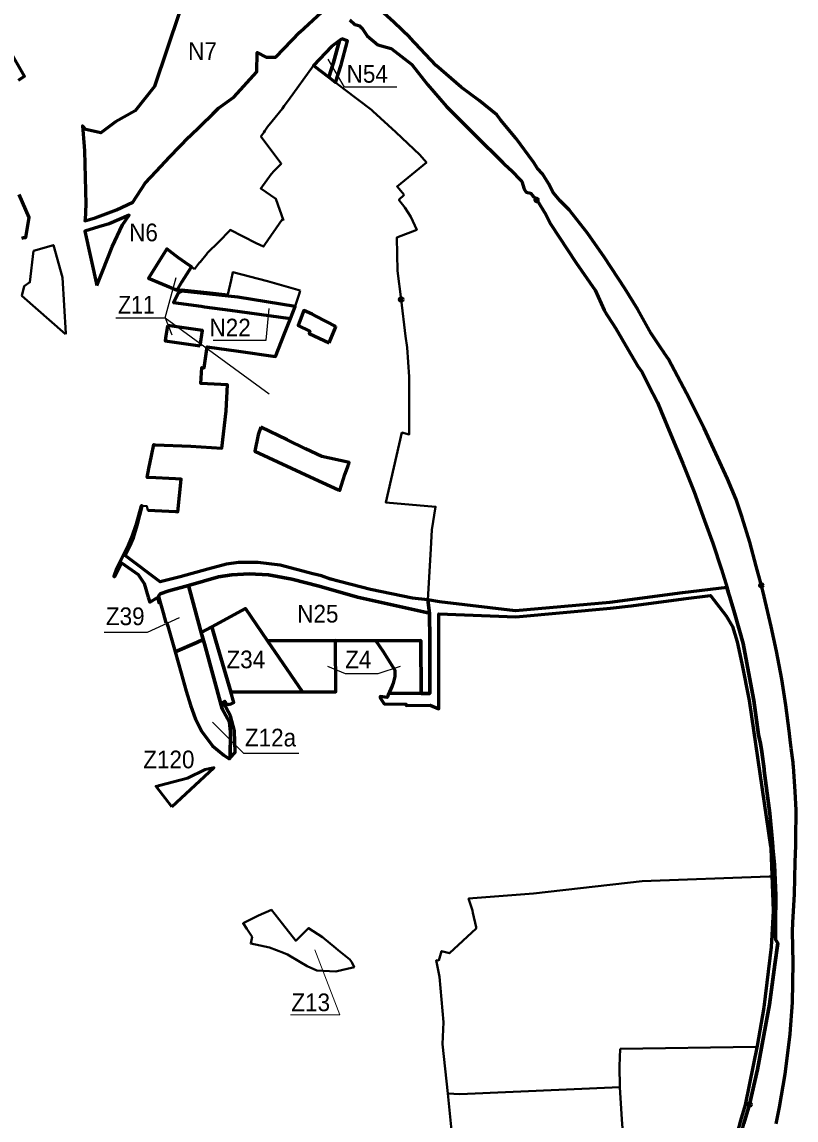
# Model space of a CAD drawing. Extents: x -650277 to -643422, y -1073980 to -1066720.
# Drawn here: x -646020 to -644970, y -1070696 to -1069207 of the extents above; entities that cross this region are included whole.
import ezdxf

# ---------------------------------------------------------------- set-up
doc = ezdxf.new("R2010")
doc.units = 0
doc.header["$LTSCALE"] = 9.6
doc.header["$PDMODE"] = 32
doc.header["$PDSIZE"] = 4.8
for name, color, linetype, lineweight in [('1', 7, 'Continuous', 60), ('11', 7, 'Continuous', 60), ('15', 7, 'Continuous', 60), ('2', 7, 'Continuous', 40), ('3', 7, 'Continuous', 60), ('40', 7, 'Continuous', 60), ('42', 7, 'Continuous', 60), ('59', 7, 'Continuous', 25), ('60', 7, 'Continuous', 60), ('63', 7, 'Continuous', 25), ('7', 7, 'Continuous', 60)]:
    doc.layers.add(name, color=color, linetype=linetype, lineweight=lineweight)

msp = doc.modelspace()

# ---------------------------------------------------------------- linework, layer by layer
at = {"layer": '1'}
msp.add_line((-645623.75, -1069825.97), (-645590.964, -1069841.09), dxfattribs=at)
at = {"layer": '1', "lineweight": 40}
msp.add_line((-645726.542, -1069939.398), (-645742.967, -1069941.862), dxfattribs=at)
for points in [[(-645668.722, -1069398.75), (-645696.19, -1069362.01), (-645692.38, -1069356.67), (-645690.81, -1069354.28), (-645687.22, -1069349), (-645680.8, -1069341.08), (-645667, -1069324.06), (-645664.89, -1069320.2), (-645658.9, -1069312.83), (-645625.11, -1069265.42), (-645604.114, -1069281.49), (-645594.94, -1069288.511)], [(-645594.94, -1069288.511), (-645583.13, -1069297.55), (-645546.19, -1069325.81), (-645544.26, -1069327.35), (-645513.41, -1069356.18), (-645480.72, -1069386.96), (-645471.738, -1069397.026), (-645511.464, -1069429.794), (-645501.878, -1069440.838)], [(-645665.58, -1069475.61), (-645675.91, -1069446.56), (-645696.45, -1069432.21), (-645682.28, -1069412.88), (-645678.06, -1069408.54), (-645668.61, -1069398.9), (-645668.722, -1069398.75)], [(-645501.878, -1069440.838), (-645508.994, -1069447.955), (-645501, -1069458), (-645493, -1069471), (-645484.783, -1069488.256), (-645512, -1069499), (-645511, -1069544), (-645506, -1069583)], [(-645786.388, -1069541.673), (-645779.376, -1069532.962), (-645778.754, -1069532.198), (-645769.369, -1069520.672), (-645768.995, -1069520.305), (-645752.715, -1069504.328), (-645738.986, -1069489.868), (-645737.897, -1069488.534), (-645702.82, -1069506.64), (-645692.87, -1069511.229), (-645690.84, -1069508.32), (-645667.31, -1069474.6), (-645665.58, -1069475.61)], [(-645836.44, -1069534.5), (-645824.05, -1069514.34), (-645811.75, -1069523.81), (-645808.1, -1069526.61), (-645799.07, -1069532.8), (-645790.62, -1069538.59), (-645786.388, -1069541.673)], [(-645810.08, -1069570.39), (-645848.78, -1069553.91), (-645836.44, -1069534.5)], [(-645643.16, -1069570.6), (-645687.29, -1069558.04), (-645734.5, -1069545.89), (-645736.8, -1069556.91), (-645741.14, -1069576.19), (-645769.04, -1069573), (-645803.513, -1069569.263), (-645810.08, -1069570.39)], [(-645676.34, -1069660.28), (-645670.23, -1069644.67), (-645664.19, -1069629.24), (-645657.52, -1069612.2), (-645656.15, -1069608.71), (-645649.91, -1069592.39), (-645648.68, -1069589.06), (-645644.56, -1069575.61), (-645643.16, -1069570.6)], [(-645506, -1069583), (-645500.137, -1069632.833), (-645500.137, -1069632.833)], [(-645500.137, -1069632.833), (-645498, -1069648), (-645495, -1069688), (-645495, -1069744), (-645495, -1069766), (-645504.976, -1069763.332), (-645527, -1069858), (-645459.312, -1069864.01), (-645464.288, -1069895.362), (-645465.756, -1069921.035), (-645469.701, -1069990.011)], [(-645839.721, -1069780.247), (-645839.658, -1069779.835), (-645791.2, -1069781.92), (-645749.48, -1069784.61), (-645743.36, -1069733.7), (-645743.01, -1069730.72), (-645741.43, -1069698.68), (-645763.24, -1069697.58), (-645777.62, -1069696.85), (-645776.45, -1069675.26), (-645773.02, -1069675.47), (-645769.36, -1069648), (-645769.264, -1069647.213), (-645726.57, -1069653.22), (-645676.34, -1069660.28)], [(-645804.185, -1069825.84), (-645804.28, -1069826.76), (-645812.18, -1069826.3), (-645847.62, -1069824.26), (-645850.63, -1069824.09), (-645848.35, -1069812.09), (-645844.57, -1069795.07), (-645841.41, -1069779.76), (-645839.658, -1069779.835), (-645839.721, -1069780.247)], [(-645742.967, -1069941.862), (-645768.424, -1069948.431), (-645833, -1069966), (-645880.431, -1069930.3), (-645874.219, -1069917.496), (-645869.262, -1069905.935), (-645863.95, -1069889.468), (-645857.289, -1069863.338), (-645857.204, -1069862.954), (-645850.92, -1069863.41), (-645849.79, -1069868.4), (-645808.84, -1069870.75), (-645808.28, -1069865.39), (-645804.185, -1069825.84)], [(-645469.701, -1069990.011), (-645490.814, -1069988.074), (-645547.4, -1069976.382), (-645614.072, -1069957.797), (-645625.979, -1069954.92), (-645670.325, -1069943.002), (-645699.889, -1069939.714), (-645726.542, -1069939.398)]]:
    msp.add_lwpolyline(points, dxfattribs=at)
at = {"layer": '1'}
for points in [[(-645836.44, -1069534.5), (-645848.78, -1069553.91), (-645810.08, -1069570.39), (-645803.07, -1069558.62), (-645790.62, -1069538.59), (-645799.07, -1069532.8), (-645808.1, -1069526.61), (-645811.75, -1069523.81), (-645824.05, -1069514.34)], [(-645639.638, -1070114.895), (-645594.733, -1070114.868), (-645595.2, -1070045.403), (-645687.31, -1070045.724)], [(-645522.587, -1070116.952), (-645478.664, -1070117.114), (-645479.429, -1070045.409), (-645540.433, -1070045.752), (-645530.3, -1070060.08), (-645514.49, -1070085.4), (-645514.56, -1070090.91), (-645514.61, -1070094.35), (-645517.02, -1070103.08), (-645518.35, -1070106.87), (-645521.73, -1070114.83)]]:
    msp.add_lwpolyline(points, close=True, dxfattribs=at)
for points in [[(-645594.58, -1069619.56), (-645621.56, -1069605.68), (-645626.95, -1069602.91), (-645638.203, -1069597.8), (-645645.715, -1069618.085), (-645629.78, -1069626.03), (-645630.93, -1069628.84), (-645603.7, -1069641.75)], [(-645849.79, -1069868.4), (-645811.848, -1069870.577), (-645808.84, -1069870.75), (-645804.28, -1069826.76), (-645812.18, -1069826.3), (-645847.62, -1069824.26), (-645850.63, -1069824.09), (-645848.35, -1069812.09), (-645844.57, -1069795.07), (-645841.41, -1069779.76), (-645839.658, -1069779.835), (-645791.2, -1069781.92), (-645749.48, -1069784.61), (-645743.36, -1069733.7), (-645741.43, -1069698.68), (-645777.62, -1069696.85), (-645776.45, -1069675.26), (-645773.02, -1069675.47), (-645769.264, -1069647.213), (-645726.57, -1069653.22), (-645676.34, -1069660.28), (-645664.19, -1069629.24), (-645656.15, -1069608.71)], [(-645823.082, -1069618.279), (-645823.13, -1069618.452), (-645825.295, -1069632.053), (-645826.133, -1069638.843), (-645826.151, -1069639.057), (-645778.45, -1069645.92)], [(-645778.45, -1069645.92), (-645775.46, -1069625.13), (-645823.082, -1069618.279)], [(-645603.7, -1069641.75), (-645594.818, -1069620.139), (-645594.58, -1069619.56)], [(-645696.517, -1069756.039), (-645700.028, -1069766.286), (-645704.355, -1069788.786), (-645623.75, -1069825.97)], [(-645578.134, -1069803.73), (-645613.84, -1069795.78), (-645635.79, -1069785.23), (-645660.57, -1069773.31), (-645696.517, -1069756.039)], [(-645590.964, -1069841.09), (-645589.23, -1069841.89), (-645582.31, -1069820.05), (-645577.52, -1069807.26), (-645576.34, -1069804.13), (-645578.134, -1069803.73)], [(-645772.853, -1070049.868), (-645774.423, -1070044.167), (-645783.063, -1070047.855), (-645812.76, -1070060.53)], [(-645737.756, -1070204.389), (-645737.624, -1070169.544), (-645738.79, -1070156.281), (-645748.62, -1070137.889), (-645772.853, -1070049.868)], [(-645812.76, -1070060.53), (-645804.52, -1070089.63), (-645797.66, -1070113.88), (-645791.72, -1070133.09), (-645784.83, -1070151.9), (-645784.83, -1070151.9)], [(-645784.83, -1070151.9), (-645776.26, -1070168.94), (-645761.78, -1070188.29), (-645746.73, -1070201.04), (-645739.12, -1070205.9), (-645737.756, -1070204.389)]]:
    msp.add_lwpolyline(points, dxfattribs=at)
at = {"layer": '1', "lineweight": 53}
msp.add_lwpolyline([(-645816.9, -1070270.96), (-645760.05, -1070217.79), (-645760.91, -1070217.98), (-645772.08, -1070220.39), (-645795.85, -1070231.81), (-645833.92, -1070241.96), (-645838.53, -1070243.19)], close=True, dxfattribs=at)
at = {"layer": '1'}
msp.add_point((-645506, -1069583), dxfattribs=at)
at = {"layer": '11'}
msp.add_lwpolyline([(-645639.638, -1070114.895), (-645687.31, -1070045.724), (-645717.36, -1070002.12), (-645762.868, -1070026.606), (-645757.215, -1070045.97), (-645737.075, -1070114.955)], close=True, dxfattribs=at)
at = {"layer": '15'}
for points in [[(-645586.39, -1069229.32), (-645589.844, -1069231.908), (-645597.738, -1069261.522), (-645604.114, -1069281.49), (-645594.94, -1069288.511), (-645587.298, -1069264.578), (-645578.713, -1069232.375)], [(-645735.532, -1069956.306), (-645712.222, -1069954.725), (-645686.147, -1069956.306), (-645654.145, -1069962.232), (-645617.403, -1069971.714), (-645565.133, -1069986.508), (-645467.472, -1070008.38), (-645469.701, -1069990.011), (-645490.814, -1069988.074), (-645547.4, -1069976.382), (-645601.753, -1069962.317), (-645614.072, -1069957.797), (-645625.979, -1069954.92), (-645670.325, -1069943.002), (-645699.889, -1069939.714), (-645726.542, -1069939.398), (-645742.967, -1069941.862), (-645768.424, -1069948.431), (-645806, -1069959), (-645833, -1069966), (-645880.431, -1069930.3), (-645874.219, -1069917.496), (-645869.262, -1069905.935), (-645863.95, -1069889.468), (-645857.289, -1069863.338), (-645857.204, -1069862.954), (-645858.78, -1069862.84), (-645865.78, -1069888.76), (-645870.89, -1069903.5), (-645876.15, -1069916.47), (-645892.09, -1069947.98), (-645895.66, -1069958.42), (-645894.25, -1069958.7), (-645885.422, -1069940.184), (-645862.782, -1069955.809), (-645854.81, -1069967.927), (-645849.1, -1069986.42), (-645847.135, -1069993.337), (-645836.64, -1069987.18), (-645834.65, -1069994.21), (-645833.32, -1069991.86), (-645835, -1069985), (-645833, -1069982), (-645821, -1069978), (-645794.679, -1069970.596), (-645753.706, -1069959.071)]]:
    msp.add_lwpolyline(points, close=True, dxfattribs=at)
for points in [[(-646025.14, -1069285.394), (-646017.15, -1069280.19), (-646037.99, -1069242.88)], [(-645061.76, -1069981.21), (-645064.052, -1069973.429), (-645124.233, -1069980.695), (-645222.809, -1069993.701), (-645350.784, -1070005.227), (-645453.852, -1069992.968), (-645469.701, -1069990.011), (-645467.472, -1070008.38), (-645467.068, -1070044.959), (-645466.96, -1070117.157), (-645478.664, -1070117.114), (-645522.587, -1070116.952), (-645524.82, -1070122.48), (-645534.63, -1070121.09), (-645534.7, -1070122.95), (-645529.17, -1070131.4), (-645499.276, -1070131.652), (-645499.142, -1070133.293), (-645466.862, -1070133.219), (-645454.881, -1070137.836), (-645455.073, -1070009.111), (-645350.591, -1070013.242), (-645221.99, -1070001.66), (-645194.003, -1069998.417), (-645123.206, -1069988.629), (-645086.484, -1069984.195), (-645065.235, -1070011.695)], [(-645033.53, -1070674.55), (-645022.64, -1070626.93), (-645014.07, -1070580.72), (-645006.44, -1070538.78), (-644998.92, -1070484.58), (-644995.14, -1070455.72), (-644998.17, -1070450.59), (-644998.25, -1070430.5), (-644997.87, -1070391.16), (-644999.47, -1070349.63), (-645001.64, -1070326.4), (-645001.81, -1070324.58), (-645002.308, -1070319.268), (-645005.98, -1070280.14), (-645013.51, -1070222.04), (-645013.77, -1070220.04), (-645016.92, -1070196.32), (-645018.56, -1070184.92), (-645021.14, -1070173.07), (-645027.49, -1070126.56), (-645032.21, -1070102.73), (-645042.27, -1070049.23), (-645047.28, -1070031.83), (-645054.73, -1070004.56), (-645060.612, -1069985.022), (-645061.76, -1069981.21)], [(-645065.235, -1070011.695), (-645056.555, -1070026.163), (-645050.293, -1070047.035), (-645043.92, -1070076.344), (-645034.122, -1070126.616), (-645004.791, -1070324.889), (-645004.523, -1070326.697)], [(-645757.215, -1070045.97), (-645762.868, -1070026.606), (-645777.143, -1070034.287), (-645772.853, -1070049.868), (-645748.62, -1070137.889)], [(-645737.63, -1070147.39), (-645747.67, -1070129.14), (-645745.29, -1070127.83), (-645744.73, -1070129), (-645743.87, -1070130.15), (-645742.67, -1070131.07), (-645741.83, -1070131.53), (-645740.89, -1070131.8), (-645739.41, -1070131.93), (-645738.41, -1070131.78), (-645737.48, -1070131.45), (-645734.77, -1070130.18), (-645732.91, -1070129.5), (-645737.075, -1070114.955), (-645757.215, -1070045.97)], [(-645748.62, -1070137.889), (-645738.79, -1070156.281), (-645737.624, -1070169.544), (-645737.756, -1070204.389)], [(-645737.756, -1070204.389), (-645731.3, -1070197.24), (-645731.94, -1070167.87), (-645737.63, -1070147.39)], [(-645004.523, -1070326.697), (-645004.434, -1070327.302), (-645001.312, -1070412.099), (-645004.327, -1070461.264), (-645014.277, -1070543.11), (-645023.048, -1070595.033), (-645039.574, -1070675.065)], [(-645039.574, -1070675.065), (-645045.493, -1070696.321), (-645059.308, -1070747.712), (-645059.403, -1070749.195), (-645053.21, -1070749.75), (-645052.4, -1070746.427), (-645046.63, -1070722.77), (-645041, -1070700.44), (-645033.53, -1070674.55)]]:
    msp.add_lwpolyline(points, dxfattribs=at)
msp.add_point((-645033.53, -1070674.55), dxfattribs=at)
at = {"layer": '2'}
for points in [[(-646017.39, -1069564.94), (-646017.39, -1069564.94), (-646009.52, -1069559.6), (-646004.7, -1069517.16)], [(-646004.7, -1069517.16), (-645977.73, -1069509.11), (-645965.36, -1069552.99), (-645960.78, -1069628.91), (-645961.36, -1069630.05)], [(-645961.36, -1069630.05), (-646020.4, -1069578.04), (-646017.39, -1069564.94)], [(-645023.048, -1070595.033), (-645014.277, -1070543.11), (-645004.327, -1070461.264), (-645001.312, -1070412.099), (-645003.03, -1070365.427), (-645003.102, -1070365.432), (-645006.86, -1070365.38), (-645179.26, -1070371.74), (-645326.62, -1070388.32), (-645414.65, -1070395.37), (-645409.38, -1070411.41), (-645408.66, -1070414.62), (-645404.34, -1070433.93), (-645404.4, -1070435.88), (-645440.61, -1070469.53), (-645451.226, -1070466.394), (-645455.09, -1070479.21), (-645458.46, -1070478.86), (-645454.02, -1070501.52), (-645448.36, -1070563), (-645449.82, -1070592.72), (-645442.834, -1070659.455)], [(-645209.41, -1070651.2), (-645209.79, -1070622.69), (-645208.96, -1070599.22)], [(-645208.96, -1070599.22), (-645025.12, -1070596.42), (-645023.346, -1070596.478), (-645023.048, -1070595.033)], [(-645442.834, -1070659.455), (-645426.34, -1070660.33), (-645209.41, -1070651.2)]]:
    msp.add_lwpolyline(points, dxfattribs=at)
for points in [[(-645594.769, -1070494.065), (-645577.47, -1070490.3), (-645571.13, -1070488.89), (-645569.97, -1070488.3), (-645572.86, -1070481.41), (-645575.7, -1070477.77), (-645591.49, -1070465.19), (-645594.62, -1070462.7), (-645612.77, -1070447.82), (-645631.63, -1070435.3), (-645636.42, -1070439.93), (-645648.9, -1070452.38), (-645666.99, -1070429.58), (-645682.02, -1070410.65), (-645699.33, -1070418.25), (-645714.74, -1070425.84), (-645720.48, -1070428.75), (-645715.56, -1070436.27), (-645708.28, -1070447.28), (-645710.14, -1070456.31), (-645684.78, -1070461.52), (-645665.6, -1070469.04), (-645660.29, -1070471.12), (-645643.4, -1070481.02), (-645633.35, -1070486.91), (-645620.22, -1070493)], [(-645442.836, -1070659.455), (-645426.34, -1070660.33), (-645209.41, -1070651.2), (-645206.7, -1070694.76), (-645204.66, -1070718.51), (-645203.13, -1070749.36), (-645202.96, -1070752.89), (-645275.236, -1070750.954), (-645282, -1070742), (-645301, -1070736), (-645324, -1070736), (-645379, -1070743), (-645415, -1070737), (-645435.711, -1070727.497)]]:
    msp.add_lwpolyline(points, close=True, dxfattribs=at)
at = {"layer": '3'}
for points in [[(-645794.679, -1069970.596), (-645821, -1069978), (-645833, -1069982), (-645835, -1069985), (-645833.32, -1069991.86)], [(-645777.143, -1070034.287), (-645786.238, -1070001.251), (-645794.679, -1069970.596)], [(-645833.32, -1069991.86), (-645828.9, -1070007.76), (-645825.08, -1070021.52)], [(-645825.08, -1070021.52), (-645823.76, -1070021.67), (-645822.549, -1070025.948), (-645812.76, -1070060.53), (-645783.063, -1070047.855), (-645774.423, -1070044.167), (-645777.143, -1070034.287)]]:
    msp.add_lwpolyline(points, dxfattribs=at)
at = {"layer": '40'}
for points in [[(-645698.83, -1069602.85), (-645656.15, -1069608.71), (-645649.91, -1069592.39), (-645727.71, -1069579.61), (-645803.33, -1069571.62), (-645808.18, -1069573.7), (-645814.82, -1069586.81), (-645777.26, -1069592.07), (-645772.58, -1069592.73), (-645738.13, -1069597.46)], [(-645595.2, -1070045.403), (-645479.429, -1070045.409), (-645478.664, -1070117.114), (-645466.96, -1070117.157), (-645467.068, -1070044.959), (-645467.472, -1070008.38), (-645565.133, -1069986.508), (-645617.403, -1069971.714), (-645654.145, -1069962.232), (-645686.147, -1069956.306), (-645712.222, -1069954.725), (-645735.532, -1069956.306), (-645753.706, -1069959.071), (-645794.679, -1069970.596), (-645786.238, -1070001.251), (-645777.143, -1070034.287), (-645762.868, -1070026.606), (-645717.36, -1070002.12), (-645687.31, -1070045.724)]]:
    msp.add_lwpolyline(points, close=True, dxfattribs=at)
at = {"layer": '42'}
msp.add_lwpolyline([(-645604.114, -1069281.49), (-645597.738, -1069261.522), (-645589.844, -1069231.908), (-645600.55, -1069239.93), (-645625.11, -1069265.42)], close=True, dxfattribs=at)
for points in [[(-646017.63, -1069499.08), (-646017.63, -1069499.08), (-646015.16, -1069498.74), (-646010.65, -1069471.91), (-646023.96, -1069440.34)], [(-646020.75, -1069500), (-646017.63, -1069499.08)]]:
    msp.add_lwpolyline(points, dxfattribs=at)
at = {"layer": '59', "lineweight": 13}
msp.add_lwpolyline([(-645656, -1070553), (-645589, -1070553), (-645623, -1070465)], dxfattribs=at)
at = {"layer": '60'}
for points in [[(-645575.58, -1069203.57), (-645568.9, -1069209.87), (-645567.07, -1069210.45), (-645562.17, -1069212.02), (-645560.72, -1069214.25), (-645559.33, -1069214.54), (-645552.2, -1069225.59), (-645537.44, -1069237.41), (-645519.59, -1069242.38), (-645491.63, -1069264.25), (-645470.44, -1069291.24), (-645444.62, -1069321.35), (-645405.7, -1069360.27), (-645368.13, -1069397.37), (-645358.04, -1069406.84), (-645342.49, -1069423.06), (-645339.31, -1069433.27), (-645336.66, -1069437.47), (-645330.57, -1069438.89), (-645327.2, -1069442.53), (-645323.36, -1069445.79), (-645322.13, -1069447.96)], [(-645017.46, -1069970.61), (-645018.28, -1069967.49), (-645024.45, -1069944.43), (-645032.85, -1069912.07), (-645043.5, -1069878.37), (-645051.78, -1069854.2), (-645063.26, -1069825.99), (-645095.1, -1069757.62), (-645118.98, -1069710.08), (-645143.56, -1069664.05), (-645148.8, -1069656.1), (-645150.3, -1069653.84), (-645153.33, -1069649.24), (-645166.67, -1069629), (-645184.88, -1069596.58), (-645202.56, -1069568.23), (-645230.1, -1069525.98), (-645253.4, -1069493.06), (-645278.31, -1069461.33), (-645281.4, -1069458.4), (-645290.5, -1069449.03), (-645299.61, -1069437.97), (-645306.16, -1069425.55), (-645314.14, -1069412.54), (-645321.1, -1069405.21), (-645326.59, -1069396.64), (-645350.63, -1069363.98), (-645371.12, -1069339.47), (-645376.38, -1069332.65), (-645400.07, -1069313.32), (-645424.8, -1069295.24), (-645458.45, -1069265.56), (-645494.13, -1069227.63), (-645515.89, -1069206.66), (-645534.25, -1069190.56)], [(-645322.13, -1069447.96), (-645309.62, -1069467.79), (-645303.57, -1069480.49), (-645268.57, -1069533.23), (-645242.75, -1069570.26), (-645230.42, -1069597.39), (-645227.27, -1069602.68), (-645225.7, -1069605.32), (-645214.76, -1069622.37), (-645198.41, -1069650.49), (-645185.17, -1069673.38), (-645179.12, -1069681.3), (-645170.3, -1069698.91), (-645158.43, -1069722.61), (-645153.44, -1069734.71), (-645140.27, -1069766.68), (-645123.84, -1069805.38), (-645108.74, -1069843.58), (-645094.42, -1069882.65), (-645083.31, -1069913.37), (-645071.53, -1069948.89), (-645063.96, -1069973.73), (-645063.23, -1069976.2), (-645062.57, -1069978.46)], [(-645062.57, -1069978.46), (-645061.76, -1069981.21), (-645060.612, -1069985.022), (-645054.73, -1070004.56), (-645047.28, -1070031.83), (-645042.27, -1070049.23), (-645032.21, -1070102.73), (-645027.49, -1070126.56), (-645021.14, -1070173.07), (-645018.56, -1070184.92), (-645016.92, -1070196.32), (-645013.77, -1070220.04), (-645013.51, -1070222.04), (-645005.98, -1070280.14), (-645002.308, -1070319.268), (-645001.81, -1070324.58), (-645001.64, -1070326.4), (-644999.47, -1070349.63), (-644997.87, -1070391.16), (-644998.25, -1070430.5), (-644998.17, -1070450.59), (-644995.14, -1070455.72), (-644998.92, -1070484.58), (-645006.44, -1070538.78), (-645014.07, -1070580.72), (-645022.64, -1070626.93), (-645033.53, -1070674.55)], [(-644996.88, -1070059.73), (-645004.02, -1070026.44), (-645010.54, -1069999.3), (-645015.548, -1069978.177), (-645016.01, -1069976.23), (-645016.89, -1069972.82), (-645017.46, -1069970.61)], [(-644997.14, -1070700.88), (-644992.6, -1070677.92), (-644985.04, -1070633.43), (-644978.44, -1070578.56), (-644975.05, -1070536.16), (-644974.44, -1070482.48), (-644975.29, -1070440.14), (-644974.69, -1070427.86), (-644972.48, -1070389.15), (-644971.37, -1070345.98), (-644970.61, -1070323.44), (-644970.55, -1070321.56), (-644970.524, -1070315.358), (-644970.36, -1070275.49), (-644971.47, -1070250.14), (-644974, -1070216.2), (-644974.29, -1070213.17), (-644974.49, -1070210.98), (-644976.94, -1070191.41), (-644978.49, -1070180.05), (-644979.57, -1070167.9), (-644984.21, -1070132.81), (-644989.62, -1070097.79), (-644996.88, -1070059.73)], [(-645033.53, -1070674.55), (-645041, -1070700.44)]]:
    msp.add_lwpolyline(points, dxfattribs=at)
for p in [(-645322.13, -1069447.96), (-645017.46, -1069970.61), (-645033.53, -1070674.55)]:
    msp.add_point(p, dxfattribs=at)
at = {"layer": '63'}
for q in [(-645817, -1069631), (-645685, -1069711)]:
    msp.add_line((-645826, -1069608), q, dxfattribs=at)
for points in [[(-645512, -1069295), (-645583, -1069295), (-645605, -1069257)], [(-645893, -1069608), (-645826, -1069608), (-645811, -1069553)], [(-645761, -1069638), (-645689, -1069638), (-645685, -1069595)], [(-645909, -1070034), (-645850, -1070034), (-645806.657, -1070014.297)], [(-645606, -1070080), (-645582, -1070090), (-645537, -1070090), (-645507, -1070080)], [(-645762, -1070156), (-645720, -1070198), (-645645, -1070198)]]:
    msp.add_lwpolyline(points, dxfattribs=at)
at = {"layer": '7'}
msp.add_line((-645918.82, -1069563.81), (-645910.9, -1069543.64), dxfattribs=at)
for points in [[(-645806.806, -1069193.112), (-645840.644, -1069294.052), (-645867.026, -1069327.317), (-645893.291, -1069341.938), (-645913.23, -1069356.892), (-645933.792, -1069352.53), (-645938.399, -1069347.452), (-645936.046, -1069375.651), (-645935.58, -1069381.24), (-645933.97, -1069453.52), (-645934.8, -1069474.71), (-645935.05, -1069476.32), (-645928.99, -1069474.55), (-645921.13, -1069472.25), (-645892.03, -1069461.43), (-645869.91, -1069451.02), (-645853.28, -1069425.27), (-645838.17, -1069409.28), (-645819.62, -1069389.66), (-645793.63, -1069362.15), (-645761.411, -1069331.17), (-645753.58, -1069323.64), (-645733.1, -1069308.58), (-645701.62, -1069274.36), (-645701.33, -1069247.86), (-645689, -1069254.5), (-645675.82, -1069254.48), (-645643.34, -1069220.59), (-645613.9, -1069193.45)], [(-645910.9, -1069543.64), (-645897.92, -1069511.49), (-645884.01, -1069481.56), (-645875.02, -1069468.52), (-645902.19, -1069480.13), (-645916.13, -1069484.55), (-645934.97, -1069490.31), (-645918.82, -1069563.81)]]:
    msp.add_lwpolyline(points, dxfattribs=at)

# ---------------------------------------------------------------- texts
at = {"layer": '1', "width": 0.95}
msp.add_text('Z120', height=24, dxfattribs=at).set_placement((-645855.898, -1070218.668))
at = {"layer": '59', "width": 0.95}
msp.add_text('Z13', height=24, dxfattribs=at).set_placement((-645655, -1070548))
at = {"layer": '63'}
for s, width, p in [('N7', 0.95, (-645795, -1069258)), ('N54', 0.95, (-645580, -1069289)), ('N6', 0.95, (-645875, -1069504)), ('Z11', 0.9, (-645890, -1069602)), ('N22', 0.95, (-645766, -1069633)), ('Z39', 0.95, (-645906.58, -1070024.53)), ('N25', 0.95, (-645647, -1070021)), ('Z34', 0.95, (-645743, -1070083)), ('Z4', 0.95, (-645582, -1070083)), ('Z12a', 0.95, (-645718, -1070189))]:
    msp.add_text(s, height=24, dxfattribs=dict(at, width=width)).set_placement(p)

doc.saveas('drawing.dxf')
